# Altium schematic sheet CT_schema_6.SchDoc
size 302 x 256 mm
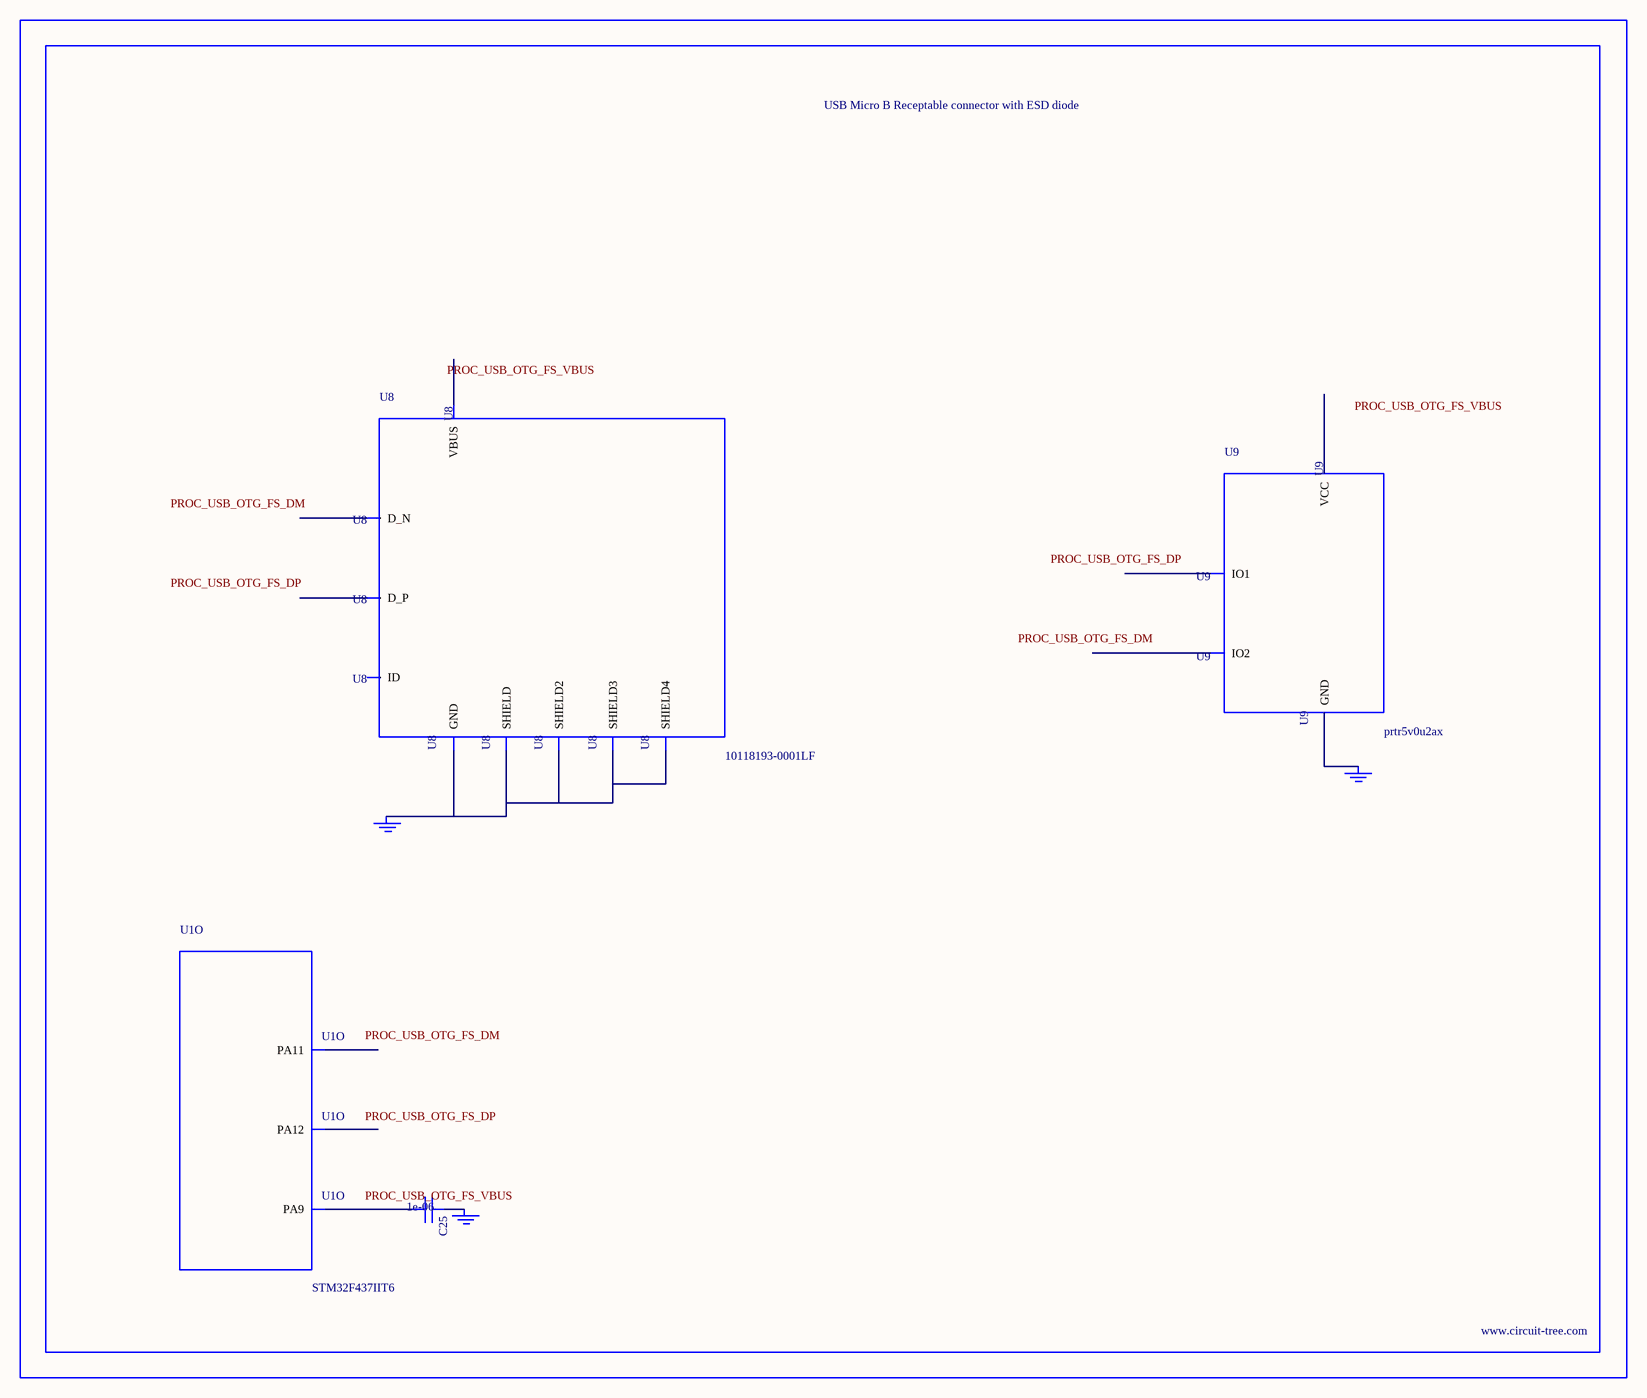
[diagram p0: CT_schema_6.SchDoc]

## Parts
BORDER5  (no value)
C25  1e-06  [C0603]
GND_INSTANCE_5_0  (no value)
GND_INSTANCE_5_1  (no value)
GND_INSTANCE_5_2  (no value)
U1  STM32F437IIT6  [LQFP176]  (part O of 16)
U8  10118193-0001LF  [FCI_10118193-0001LF]
U9  prtr5v0u2ax  [SOT143B]

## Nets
NetC25_1: C25.1 GND_INSTANCE_5_1.0(GND)
NetC25_2: C25.2 U1.120(PA9)
NetGND_INSTANCE_5_0_0: GND_INSTANCE_5_0.0(GND) U8.5(GND) U8.6(SHIELD) U8.7(SHIELD2) U8.8(SHIELD3) U8.9(SHIELD4)
NetGND_INSTANCE_5_2_0: GND_INSTANCE_5_2.0(GND) U9.1(GND)

Not connected (* = marked no-connect by the designer): U1 122(PA11) 123(PA12); U8 1(VBUS) 2(D_N) 3(D_P) 4(ID); U9 2(IO1) 3(IO2) 4(VCC)

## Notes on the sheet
- Labels drawn without touching a wire or pin: PROC_USB_OTG_FS_DM, PROC_USB_OTG_FS_DP, PROC_USB_OTG_FS_VBUS

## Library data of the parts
BORDER5 = BORDER_PAGE5
C25 = C0603C105K3RACTU
GND_INSTANCE_5_0-GND_INSTANCE_5_2 = GND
